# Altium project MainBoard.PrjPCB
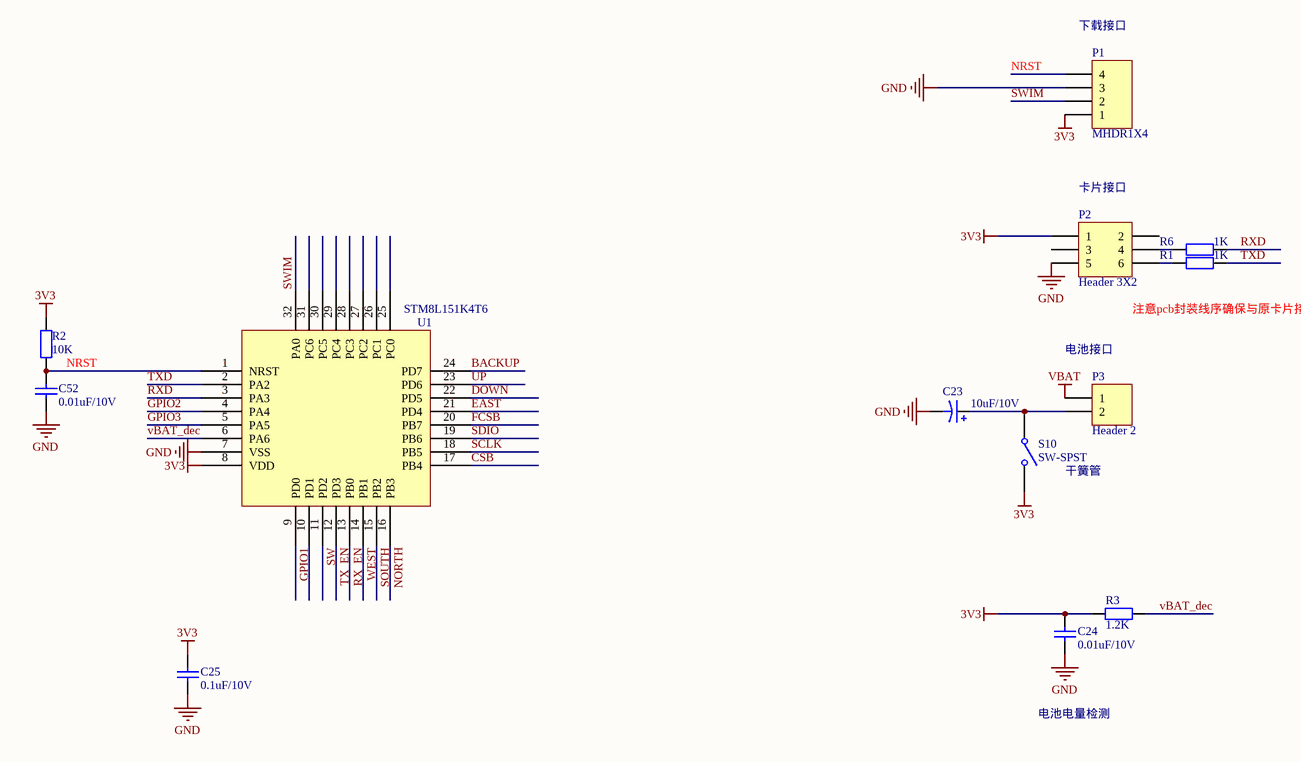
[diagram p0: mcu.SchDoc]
3 sheets, 119 parts. Net scope: global (net labels, ports and power ports of the same name join across sheets).
Sheets:
  mcu.SchDoc
  RF.SchDoc
  power.SchDoc

## Sheet mcu.SchDoc
size A3

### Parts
(Parts that share a designator on the sheet are numbered #1, #2 ... from top to bottom, then left to right.)
C23#1  10uF/10V
C24  0.01uF/10V  [0603C]
C25  0.1uF/10V  [0603C]
C52  0.01uF/10V  [0603C]
P1  MHDR1X4  [SIP4]
P2  Header 3X2
P3  Header 2
R1#1  1K  [0603R]
R2  10K  [0603R]
R3  1.2K  [0603R]
R6  1K  [0603R]
S10  SW-SPST
U1  STM8L151K4T6  [QFP80P900X900X245-32N]

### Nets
3V3: C24.1 C25.1 P1.1 P2.1 R2.2 R3.2 S10.2(NO) U1.8(VDD)
GND: C23#1.2 C24.2 C25.2 C52.2 P1.3 P2.5 U1.7(VSS)
VBAT: P3.1
BACKUP: U1.24(PD7)
CSB: U1.17(PB4)
DOWN: U1.22(PD5)
EAST: U1.21(PD4)
FCSB: U1.20(PB7)
GPIO1: U1.9(PD0)
GPIO2: U1.4(PA4)
GPIO3: U1.5(PA5)
NORTH: U1.16(PB3)
NRST: C52.1 P1.4 R2.1 U1.1(NRST)
RX_EN: U1.13(PB0)
RXD: R6.1 U1.3(PA3)
SCLK: U1.18(PB5)
SDIO: U1.19(PB6)
SOUTH: U1.15(PB2)
SW: U1.11(PD2)
SWIM: P1.2 U1.32(PA0)
TX_EN: U1.12(PD3)
TXD: R1#1.1 U1.2(PA2)
UP: U1.23(PD6)
vBAT_dec: R3.1 U1.6(PA6)
WEST: U1.14(PB1)
NetC23#1_1: C23#1.1 P3.2 S10.1(COMMON)
NetP2_4: P2.4 R6.2
NetP2_6: P2.6 R1#1.2

Not connected (* = marked no-connect by the designer): P2 2 3; U1 10(PD1) 25(PC0) 26(PC1) 27(PC2) 28(PC3) 29(PC4) 30(PC5) 31(PC6)

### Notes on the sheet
- (near P1) 下载接口
- (near P2) 卡片接口
- 注意pcb封装线序确保与原卡片接口一致
- (near P3) 电池接口
- 干簧管
- 电池电量检测

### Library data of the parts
C23#1 = Cap Pol1: Polarized Capacitor (Radial); Value: 100pF
C24 C25 C52 = Cap: Capacitor; Value: 106
P1 = MHDR1X4: Header, 4-Pin
P2 = Header 3X2: Header, 3-Pin, Dual row
P3 = Header 2: Header, 2-Pin
R1#1 R2 R3 R6 = Res2: Resistor; Value: 10K/5%/1/8W
S10 = SW-SPST: Single-Pole, Single-Throw Switch

## Sheet RF.SchDoc
size A3
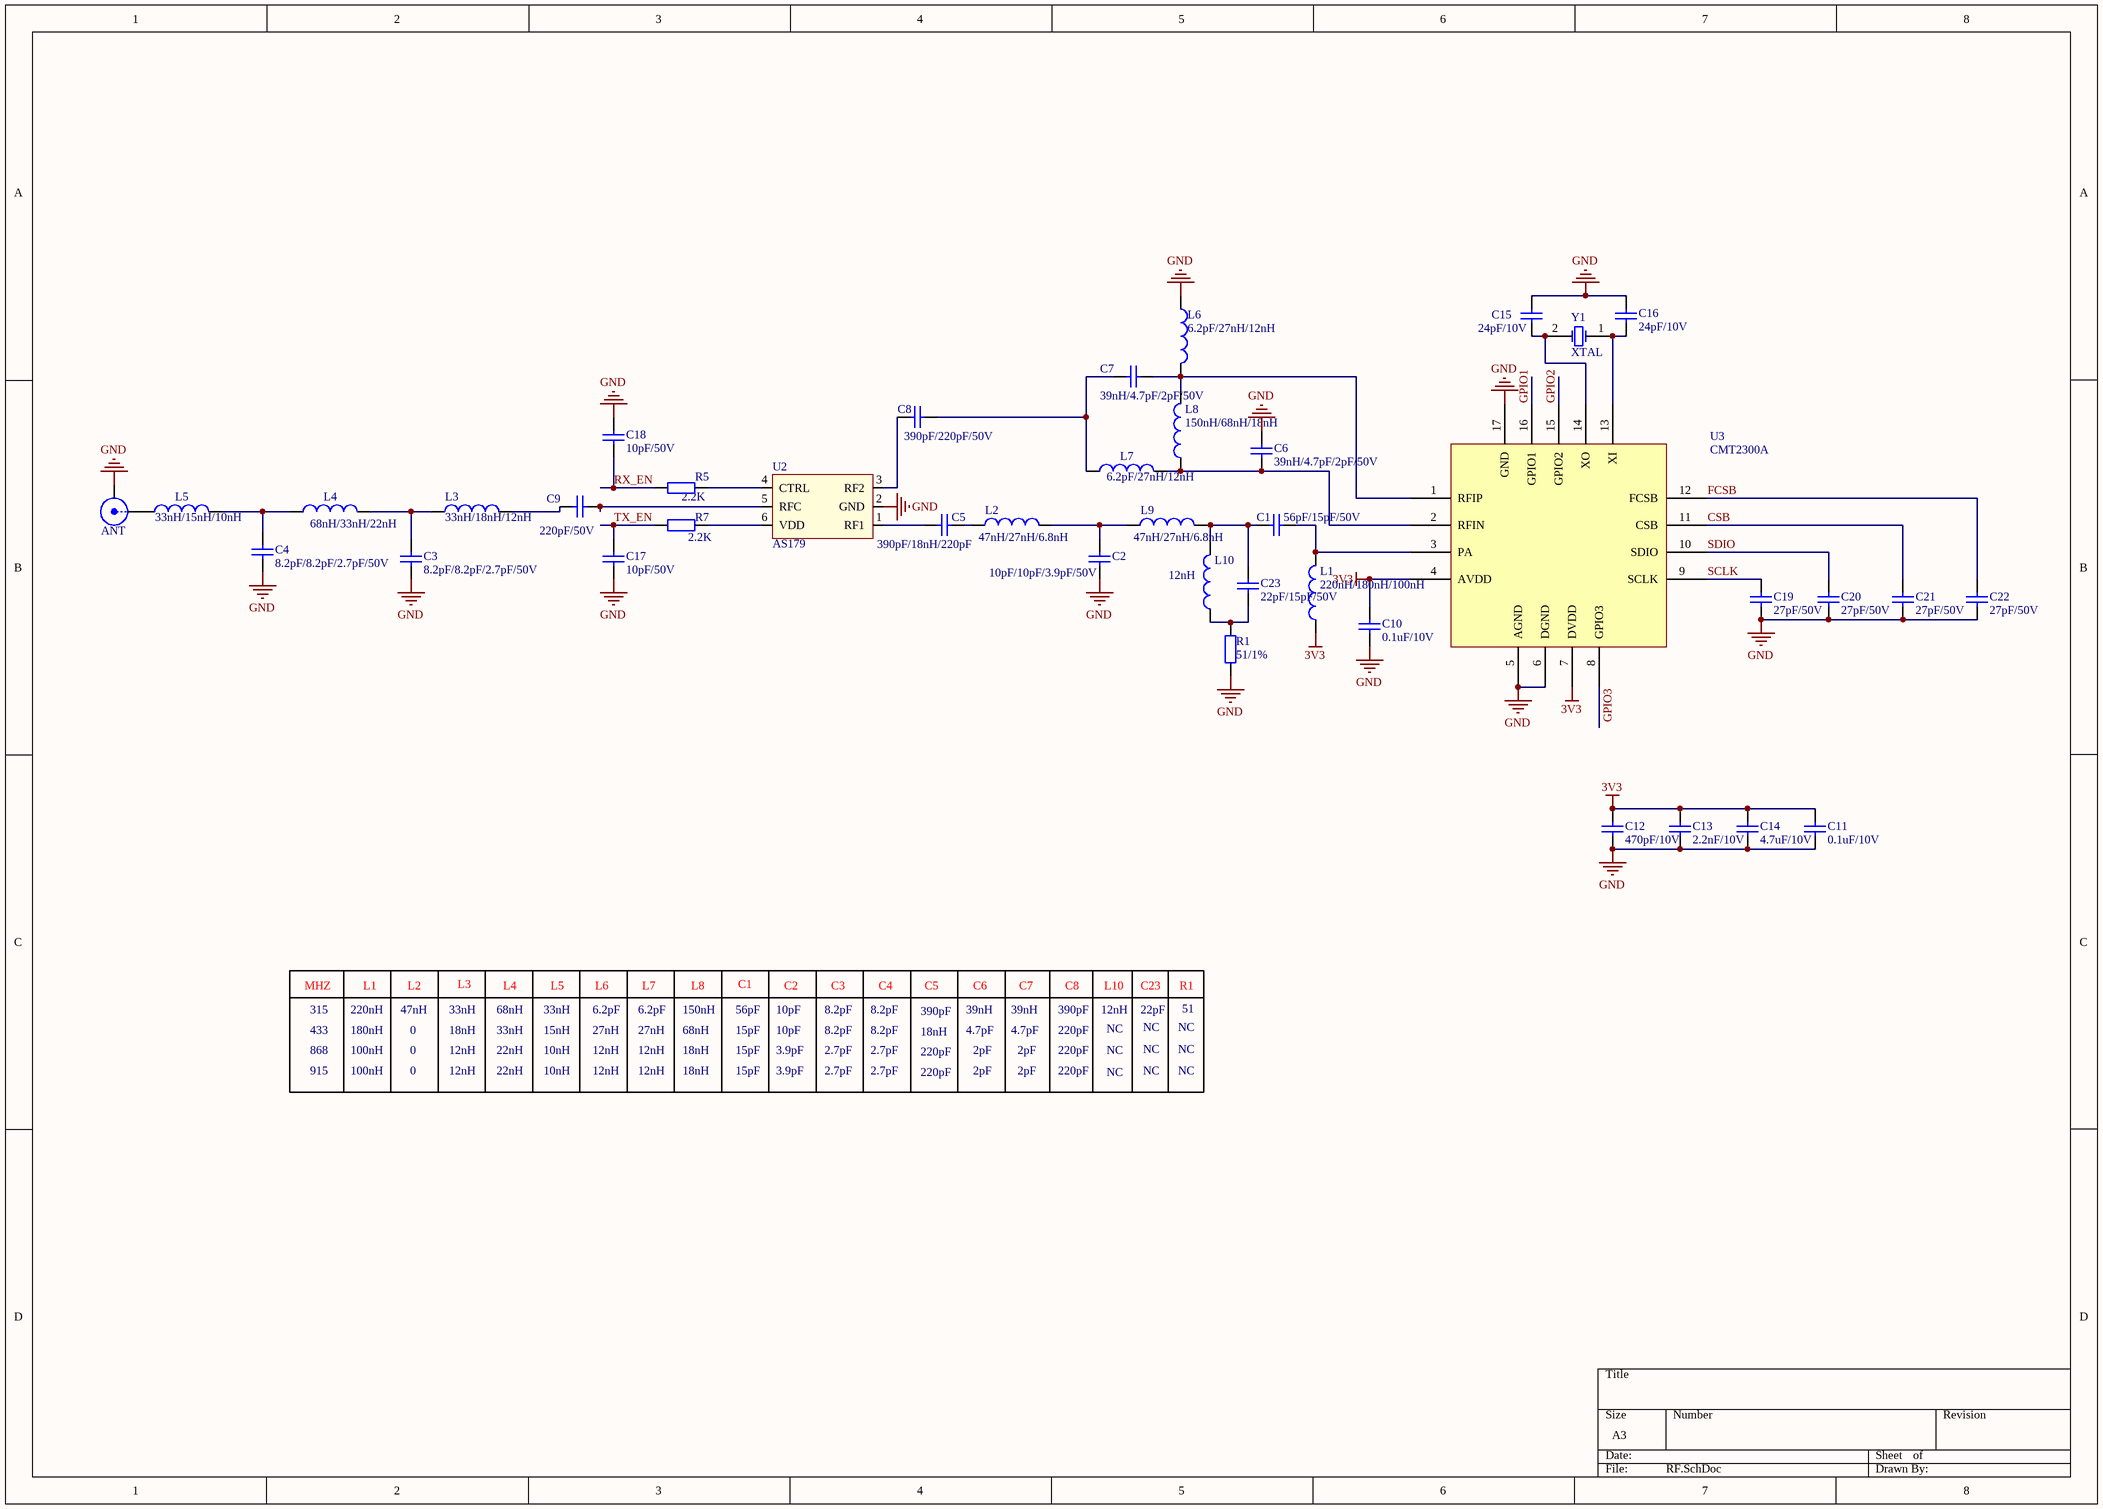
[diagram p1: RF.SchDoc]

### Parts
(Parts that share a designator on the sheet are numbered #1, #2 ... from top to bottom, then left to right.)
ANT  (no value)  [SMA Straight SMD]
C1  56pF/15pF/50V  [0603C]
C2  10pF/10pF/3.9pF/50V  [0603C]
C3  8.2pF/8.2pF/2.7pF/50V  [0603C]
C4  8.2pF/8.2pF/2.7pF/50V  [0603C]
C5  390pF/18nH/220pF  [0603C]
C6  39nH/4.7pF/2pF/50V  [0603C]
C7  39nH/4.7pF/2pF/50V  [0603C]
C8  390pF/220pF/50V  [0603C]
C9  220pF/50V  [0603C]
C10  0.1uF/10V  [0603C]
C11  0.1uF/10V  [0603C]
C12  470pF/10V  [0603C]
C13  2.2nF/10V  [0603C]
C14  4.7uF/10V  [0603C]
C15  24pF/10V  [0603C]
C16  24pF/10V  [0603C]
C17  10pF/50V  [0603C]
C18  10pF/50V  [0603C]
C19  27pF/50V  [0603C]
C20  27pF/50V  [0603C]
C21  27pF/50V  [0603C]
C22  27pF/50V  [0603C]
C23#2  22pF/15pF/50V  [0603C]
L1  220nH/180nH/100nH  [0603R]
L2  47nH/27nH/6.8nH  [0603R]
L3  33nH/18nH/12nH  [0603R]
L4  68nH/33nH/22nH  [0603R]
L5  33nH/15nH/10nH  [0603R]
L6  6.2pF/27nH/12nH  [0603R]
L7  6.2pF/27nH/12nH  [0603R]
L8  150nH/68nH/18nH  [0603R]
L9  47nH/27nH/6.8nH  [0603R]
L10  12nH  [0603R]
R1#2  51/1%  [0603R]
R5  2.2K  [0603R]
R7  2.2K  [0603R]
U2  AS179
U3  CMT2300A
Y1  XTAL  [BCY-W2/D3.1]

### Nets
3V3: C10.1 C11.1 C12.1 C13.1 C14.1 L1.1 U3.4(AVDD) U3.7(DVDD)
GND: ANT.2(GND) C2.1 C3.2 C4.2 C6.2 C10.2 C11.2 C12.2 C13.2 C14.2 C15.1 C16.1 C17.1 C18.2 C19.2 C20.2 C21.2 C22.2 L6.1 R1#2.2 U2.2(GND) U3.5(AGND) U3.6(DGND) U3.17(GND)
CSB: C21.1 U3.11(CSB)
FCSB: C22.1 U3.12(FCSB)
GPIO1: U3.16(GPIO1)
GPIO2: U3.15(GPIO2)
GPIO3: U3.8(GPIO3)
RX_EN: C18.1 R5.2
SCLK: C19.1 U3.9(SCLK)
SDIO: C20.1 U3.10(SDIO)
TX_EN: C17.2 R7.2
NetANT_1: ANT.1(Signal) L5.1
NetC1_1: C1.1 C23#2.2 L9.2 L10.2
NetC1_2: C1.2 L1.2 U3.3(PA)
NetC2_2: C2.2 L2.2 L9.1
NetC3_1: C3.1 L3.1 L4.2
NetC4_1: C4.1 L4.1 L5.2
NetC5_1: C5.1 U2.1(RF1)
NetC5_2: C5.2 L2.1
NetC6_1: C6.1 L7.2 L8.1 U3.2(RFIN)
NetC7_1: C7.1 C8.2 L7.1
NetC7_2: C7.2 L6.2 L8.2 U3.1(RFIP)
NetC8_1: C8.1 U2.3(RF2)
NetC9_1: C9.1 U2.5(RFC)
NetC9_2: C9.2 L3.2
NetC15_2: C15.2 U3.14(XO) Y1.2(OSC2)
NetC16_2: C16.2 U3.13(XI) Y1.1(OSC1)
NetC23#2_1: C23#2.1 L10.1 R1#2.1
NetR5_1: R5.1 U2.4(CTRL)
NetR7_1: R7.1 U2.6(VDD)

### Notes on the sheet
- MHZ
- L1
- L2
- L3
- L4
- L5
- L6
- L7
- L8
- C1
- C2
- C3
- C4
- C5
- C6
- C7
- C8
- L10
- C23
- R1
- 315
- 433
- 868
- 220nH
- 180nH
- 100nH
- 47nH
- 0
- 33nH
- 18nH
- 12nH
- 68nH
- 22nH
- 15nH
- 10nH
- 6.2pF
- 27nH
- 150nH
- 56pF
- 15pF
- 10pF
- 3.9pF
- 8.2pF
- 2.7pF
- 390pF
- 220pF
- 39nH
- 4.7pF
- 2pF
- NC
- 22pF
- 51
- 915

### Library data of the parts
ANT = SMA: SMA Straight Connector
C1-C22 C23#2 = Cap: Capacitor; Value: 106
L1-L10 = Inductor: Code_IEC: 1005; Value: 10mH
R1#2 R5 R7 = Res2: Resistor; Value: 10K/5%/1/8W
U2 = PE4259 RF Switch: PE4259 Peregrine RF Switch
Y1 = XTAL: Crystal Oscillator

## Sheet power.SchDoc
size A2
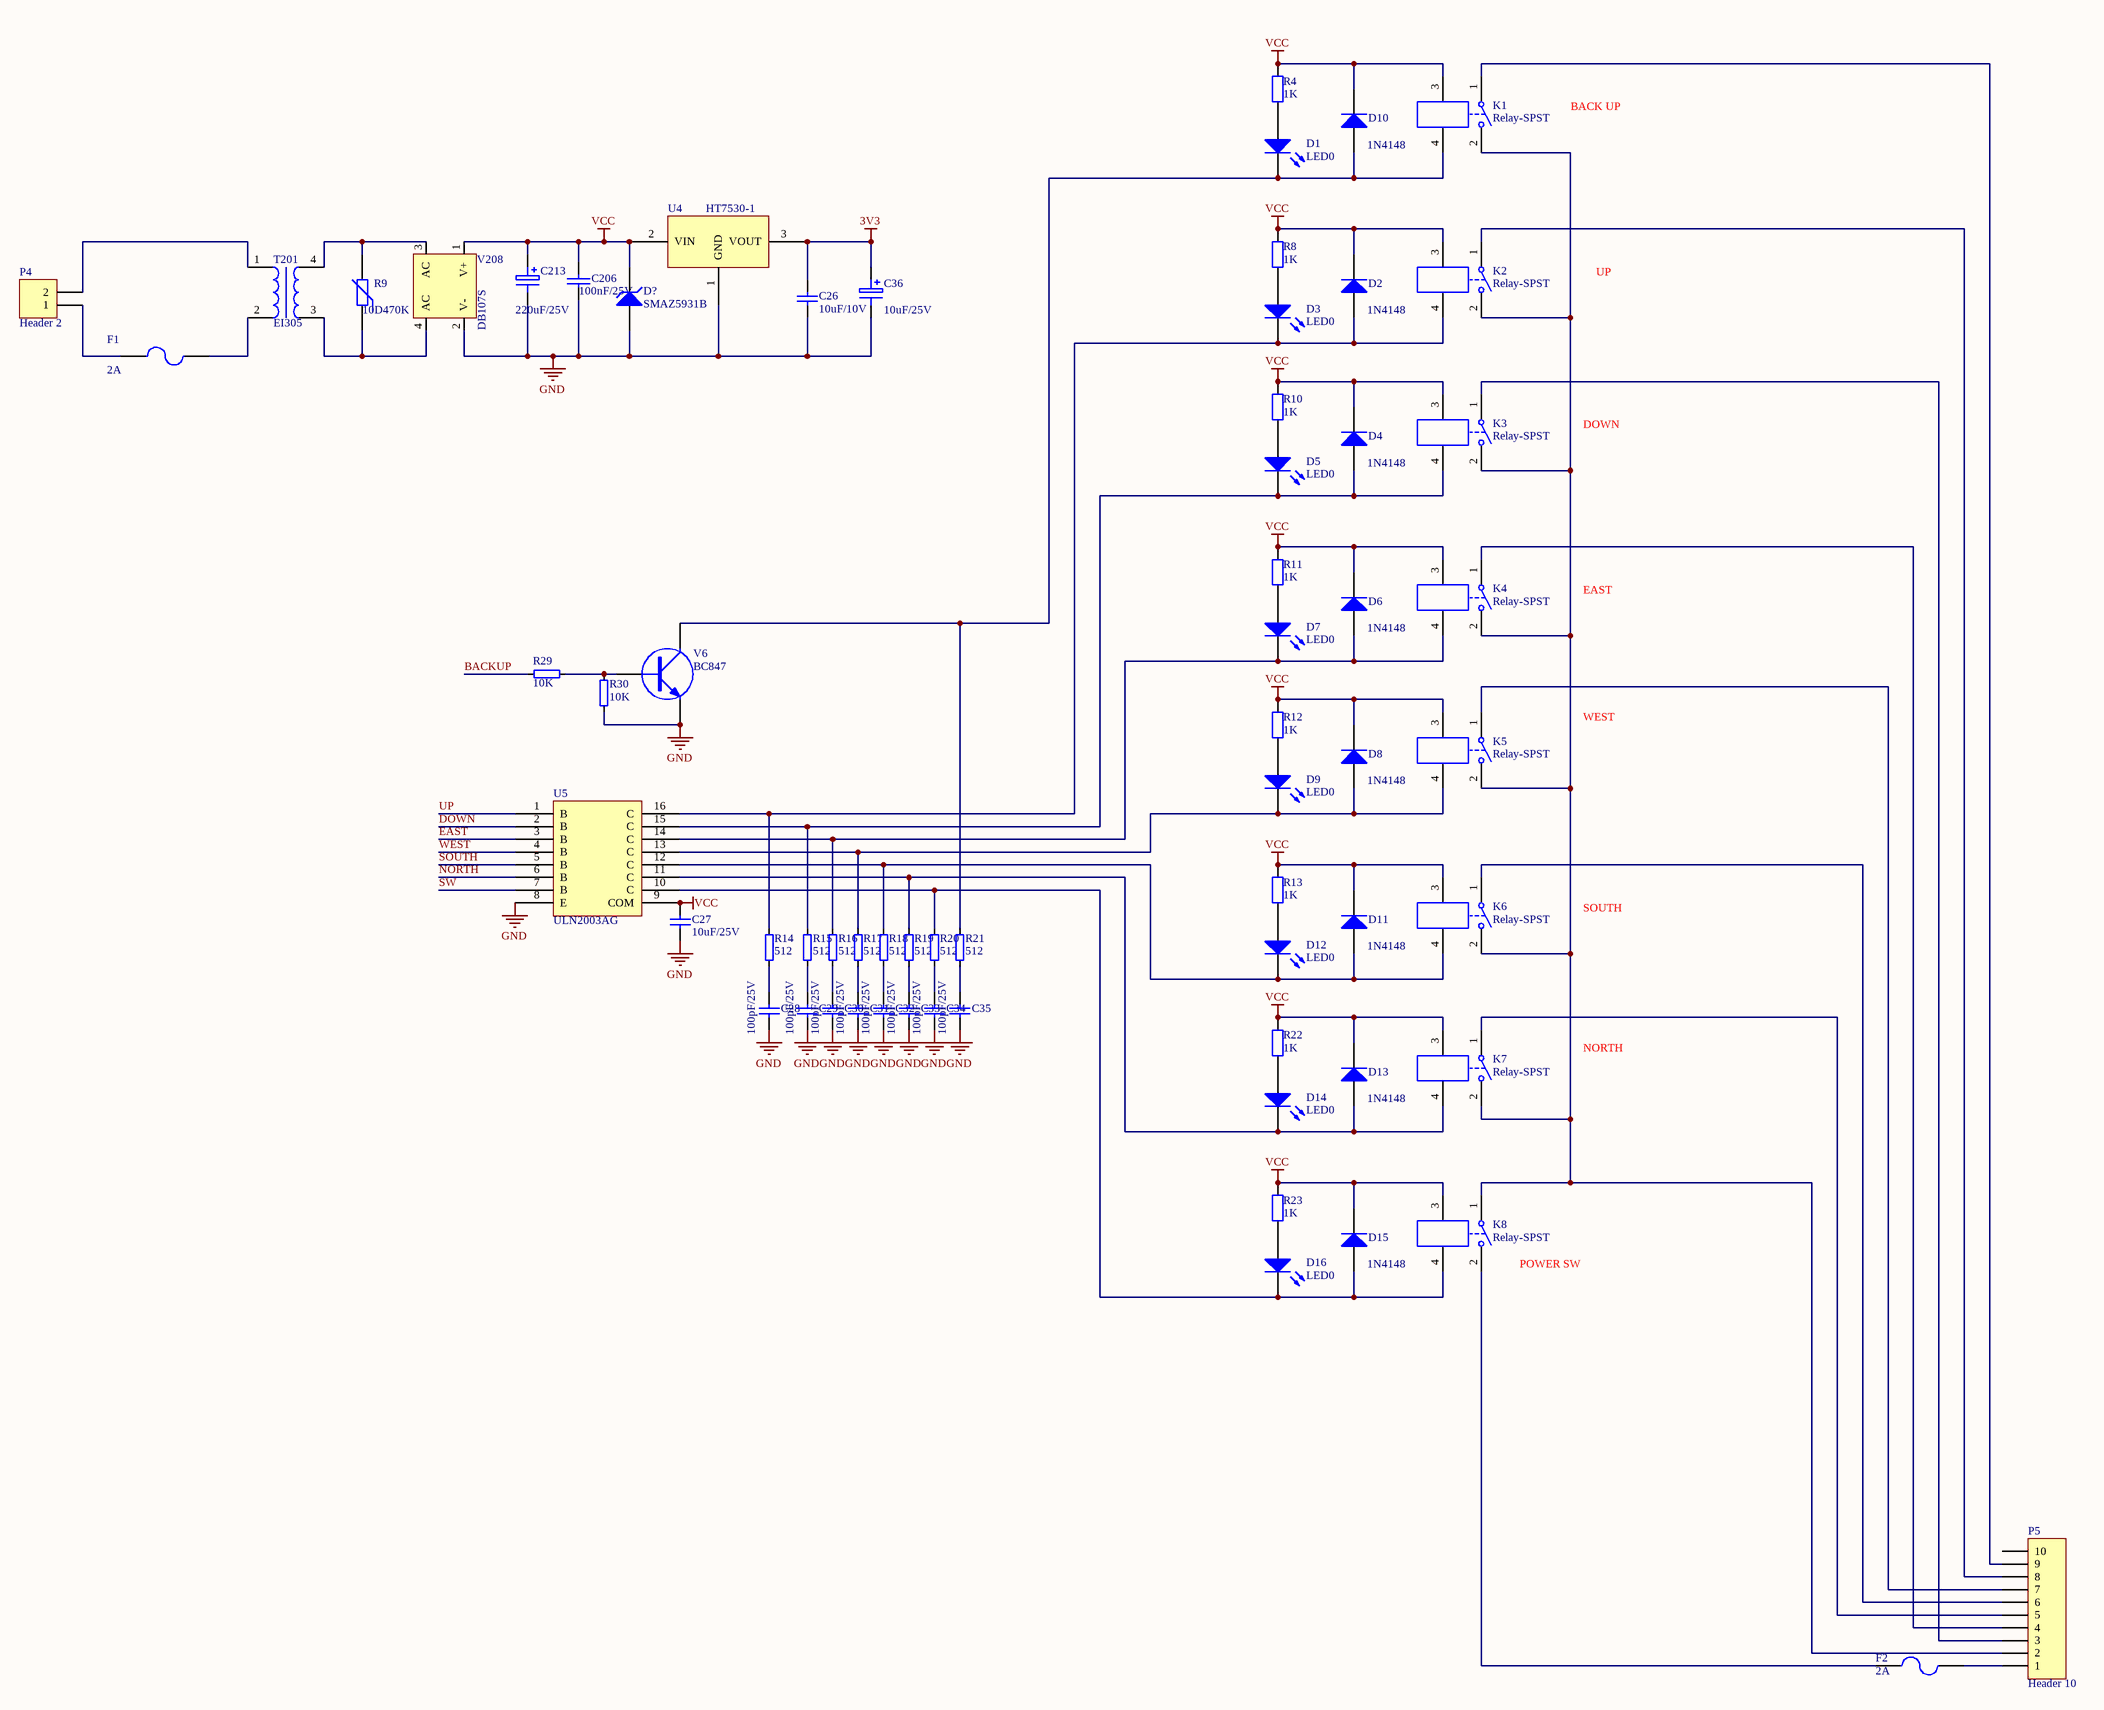
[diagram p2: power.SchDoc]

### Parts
C26  10uF/10V  [0603C]
C27  10uF/25V
C28  100pF/25V
C29  100pF/25V
C30  100pF/25V
C31  100pF/25V
C32  100pF/25V
C33  100pF/25V
C34  100pF/25V
C35  100pF/25V
C36  10uF/25V
C206  100nF/25V
C213  220uF/25V
D1  LED0  [0603led]
D2  1N4148  [SMD-D]
D3  LED0  [0603led]
D4  1N4148  [SMD-D]
D5  LED0  [0603led]
D6  1N4148  [SMD-D]
D7  LED0  [0603led]
D8  1N4148  [SMD-D]
D9  LED0  [0603led]
D10  1N4148  [SMD-D]
D11  1N4148  [SMD-D]
D12  LED0  [0603led]
D13  1N4148  [SMD-D]
D14  LED0  [0603led]
D15  1N4148  [SMD-D]
D16  LED0  [0603led]
D?  SMAZ5931B  [SMA]
F1  2A  [FU]
F2  2A  [FU]
K1  Relay-SPST  [KKK]
K2  Relay-SPST  [KKK]
K3  Relay-SPST  [KKK]
K4  Relay-SPST  [KKK]
K5  Relay-SPST  [KKK]
K6  Relay-SPST  [KKK]
K7  Relay-SPST  [KKK]
K8  Relay-SPST  [KKK]
P4  Header 2  [CH022]
P5  Header 10  [CN10]
R4  1K  [0603R]
R8  1K  [0603R]
R9  10D470K
R10  1K  [0603R]
R11  1K  [0603R]
R12  1K  [0603R]
R13  1K  [0603R]
R14  512  [0603R]
R15  512  [0603R]
R16  512  [0603R]
R17  512  [0603R]
R18  512  [0603R]
R19  512  [0603R]
R20  512  [0603R]
R21  512  [0603R]
R22  1K  [0603R]
R23  1K  [0603R]
R29  10K  [0603R]
R30  10K  [0603R]
T201  EI305  [T01]
U4  HT7530-1
U5  ULN2003AG
V6  BC847  [SOT-23]
V208  DB107S  [BRIDGE]

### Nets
3V3: C26.1 C36.1 U4.3(VOUT)
GND: C26.2 C27.2 C28.2 C29.2 C30.2 C31.2 C32.2 C33.2 C34.2 C35.2 C36.2 C206.2 C213.2 D?.1(A) R30.2 U4.1(GND) U5.8(E) V6.2(E) V208.2(V-)
VCC: C27.1 C206.1 C213.1 D2.2(K) D4.2(K) D6.2(K) D8.2(K) D10.2(K) D11.2(K) D13.2(K) D15.2(K) D?.2(K) K1.3 K2.3 K3.3 K4.3 K5.3 K6.3 K7.3 K8.3 R4.2 R8.2 R10.2 R11.2 R12.2 R13.2 R22.2 R23.2 U4.2(VIN) U5.9(COM) V208.1(V+)
BACKUP: R29.1
DOWN: U5.2(B)
EAST: U5.3(B)
NORTH: U5.6(B)
SOUTH: U5.5(B)
SW: U5.7(B)
UP: U5.1(B)
WEST: U5.4(B)
NetC28_1: C28.1 R14.2
NetC29_1: C29.1 R15.2
NetC30_1: C30.1 R16.2
NetC31_1: C31.1 R17.2
NetC32_1: C32.1 R18.2
NetC33_1: C33.1 R19.2
NetC34_1: C34.1 R20.2
NetC35_1: C35.1 R21.2
NetD1_1: D1.1(A) R4.1
NetD1_2: D1.2(K) D10.1(A) K1.4 R21.1 V6.3(C)
NetD2_1: D2.1(A) D3.2(K) K2.4 R14.1 U5.16(C)
NetD3_1: D3.1(A) R8.1
NetD4_1: D4.1(A) D5.2(K) K3.4 R15.1 U5.15(C)
NetD5_1: D5.1(A) R10.1
NetD6_1: D6.1(A) D7.2(K) K4.4 R16.1 U5.14(C)
NetD7_1: D7.1(A) R11.1
NetD8_1: D8.1(A) D9.2(K) K5.4 R17.1 U5.13(C)
NetD9_1: D9.1(A) R12.1
NetD11_1: D11.1(A) D12.2(K) K6.4 R18.1 U5.12(C)
NetD12_1: D12.1(A) R13.1
NetD13_1: D13.1(A) D14.2(K) K7.4 R19.1 U5.11(C)
NetD14_1: D14.1(A) R22.1
NetD15_1: D15.1(A) D16.2(K) K8.4 R20.1 U5.10(C)
NetD16_1: D16.1(A) R23.1
NetF1_1: F1.1 P4.1
NetF1_2: F1.2 T201.2
NetF2_1: F2.1 K8.2
NetF2_2: F2.2 P5.1
NetK1_1: K1.1 P5.9
NetK1_2: K1.2 K2.2 K3.2 K4.2 K5.2 K6.2 K7.2 K8.1 P5.2
NetK2_1: K2.1 P5.8
NetK3_1: K3.1 P5.3
NetK4_1: K4.1 P5.4
NetK5_1: K5.1 P5.7
NetK6_1: K6.1 P5.6
NetK7_1: K7.1 P5.5
NetP4_2: P4.2 T201.1
NetR9_1: R9.1 T201.3 V208.4(AC)
NetR9_2: R9.2 T201.4 V208.3(AC)
NetR29_2: R29.2 R30.1 V6.1(B)

Not connected (* = marked no-connect by the designer): P5 10

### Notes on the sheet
- BACK UP
- UP
- DOWN
- EAST
- WEST
- SOUTH
- NORTH
- (near K8) POWER SW

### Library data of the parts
C26-C35 = Cap: Capacitor; Value: 106
C36 C213 = ELECTRO1: Electrolytic Capacitor
C206 = CAP: Capacitor
D1 D3 D5 D7 D9 D12 D14 D16 = LED0: Typical INFRARED GaAs LED
D2 D4 D6 D8 D10 D11 D13 D15 = Diode: Default Diode
D? = D Zener: Zener Diode
F1 F2 = Fuse 2: Fuse
K1-K8 = Relay-SPST: Single-Pole Single-Throw Relay
P4 = Header 2: Header, 2-Pin
P5 = Header 10: Header, 10-Pin
R4 R8 R10-R13 R22 R23 = Res2: Resistor; Value: 10K/5%/1/8W
R9 = Res Varistor: Varistor (Voltage-Sensitive Resistor)
R14-R21 R29 R30 = RES2
U4 = HT7533-1
V6 = NPN: NPN Transistor
V208 = BRIDGE2: Diode Bridge

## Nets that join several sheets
3V3: mcu (8 pins), RF (8 pins), power (C26.1 C36.1 U4.3)
GND: mcu (7 pins), RF (24 pins), power (19 pins)
BACKUP: mcu (U1.24), power (R29.1)
CSB: mcu (U1.17), RF (C21.1 U3.11)
DOWN: mcu (U1.22), power (U5.2)
EAST: mcu (U1.21), power (U5.3)
FCSB: mcu (U1.20), RF (C22.1 U3.12)
GPIO1: mcu (U1.9), RF (U3.16)
GPIO2: mcu (U1.4), RF (U3.15)
GPIO3: mcu (U1.5), RF (U3.8)
NORTH: mcu (U1.16), power (U5.6)
RX_EN: mcu (U1.13), RF (C18.1 R5.2)
SCLK: mcu (U1.18), RF (C19.1 U3.9)
SDIO: mcu (U1.19), RF (C20.1 U3.10)
SOUTH: mcu (U1.15), power (U5.5)
SW: mcu (U1.11), power (U5.7)
TX_EN: mcu (U1.12), RF (C17.2 R7.2)
UP: mcu (U1.23), power (U5.1)
WEST: mcu (U1.14), power (U5.4)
